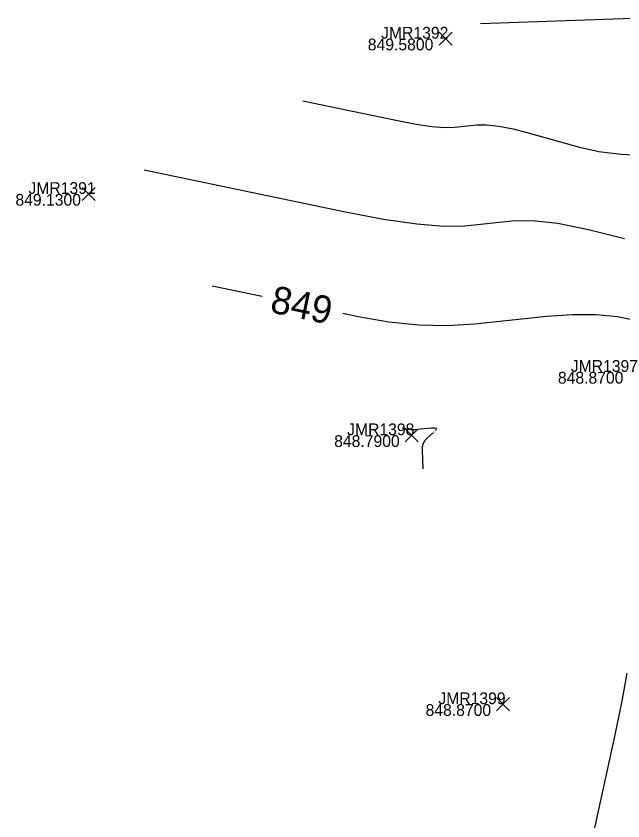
# Model space of a CAD drawing. Extents: x 1654928 to 1810050, y 486881 to 626330.
# Drawn here: x 1801235.5 to 1801297.5, y 489876.6 to 489958.8 of the extents above; entities that cross this region are included whole.
import ezdxf

# ---------------------------------------------------------------- set-up
doc = ezdxf.new("R2010")
doc.units = 0
for name, color, linetype in [('DT_X_Contour_Major', 7, 'Continuous'), ('DT_X_Contour_Minor', 7, 'Continuous'), ('SV_X_Random_Point', 7, 'Continuous'), ('SV_X_Text_Elevation', 7, 'Continuous'), ('SV_X_Text_Name', 7, 'Continuous')]:
    doc.layers.add(name, color=color, linetype=linetype)

msp = doc.modelspace()

# ---------------------------------------------------------------- linework, layer by layer
at = {"layer": 'DT_X_Contour_Major'}
for points in [[(1801260.643, 489930.139), (1801255.532, 489931.208)], [(1801298.897, 489927.653), (1801296.933, 489928.07), (1801294.743, 489928.285), (1801292.327, 489928.298), (1801289.685, 489928.108), (1801282.339, 489927.335), (1801279.529, 489927.164), (1801276.609, 489927.233), (1801273.58, 489927.542), (1801270.44, 489928.09), (1801268.866, 489928.419)], [(1801292.361, 489865.603), (1801296.572, 489884.906), (1801297.355, 489888.668), (1801297.902, 489891.68)]]:
    msp.add_lwpolyline(points, dxfattribs=at)
at = {"layer": 'DT_X_Contour_Minor'}
for points in [[(1801282.925, 489958.029), (1801304.313, 489958.787)], [(1801264.785, 489950.144), (1801274.44, 489948.125), (1801276.357, 489947.758), (1801277.97, 489947.521), (1801279.281, 489947.415), (1801280.287, 489947.44), (1801282.567, 489947.68), (1801283.55, 489947.693), (1801284.787, 489947.553), (1801286.28, 489947.259), (1801288.028, 489946.811), (1801293.028, 489945.412), (1801295.031, 489944.966), (1801297.288, 489944.677), (1801299.798, 489944.544)], [(1801248.586, 489943.096), (1801268.968, 489938.834), (1801273.015, 489938.058), (1801276.422, 489937.559), (1801279.188, 489937.335), (1801281.313, 489937.387), (1801286.126, 489937.894), (1801288.2, 489937.922), (1801290.813, 489937.626), (1801293.964, 489937.005), (1801297.654, 489936.06)], [(1801278.393, 489916.516), (1801278.409, 489916.533), (1801278.42, 489916.66), (1801278.258, 489916.719), (1801277.922, 489916.709), (1801276.798, 489916.59), (1801276.41, 489916.555), (1801276.09, 489916.539), (1801275.837, 489916.543), (1801275.651, 489916.565), (1801274.941, 489916.713)], [(1801277.076, 489912.556), (1801277, 489914.451), (1801277.019, 489914.835), (1801277.11, 489915.176), (1801277.272, 489915.472), (1801277.506, 489915.724), (1801278.092, 489916.223)]]:
    msp.add_lwpolyline(points, dxfattribs=at)
at = {"layer": 'SV_X_Random_Point'}
for p, q in [((1801278.697, 489955.82), (1801280.031, 489957.155)), ((1801278.697, 489957.155), (1801280.031, 489955.82)), ((1801242.25, 489939.962), (1801243.583, 489941.297)), ((1801242.25, 489941.297), (1801243.583, 489939.962)), ((1801275.245, 489915.321), (1801276.578, 489916.656)), ((1801275.245, 489916.656), (1801276.578, 489915.321)), ((1801284.563, 489887.857), (1801285.896, 489889.192)), ((1801284.563, 489889.192), (1801285.896, 489887.857))]:
    msp.add_line(p, q, dxfattribs=at)

# ---------------------------------------------------------------- texts
at = {"layer": 'DT_X_Contour_Major'}
msp.add_text('849', height=2.8, rotation=348.18836, dxfattribs=at).set_placement((1801261.328, 489928.565))
at = {"layer": 'DT_X_Contour_Minor'}
msp.add_text('849', height=0.14, rotation=224.18533, dxfattribs=at).set_placement((1801278.316, 489916.524))
at = {"layer": 'SV_X_Text_Elevation'}
for s, p in [('849.5800', (1801271.418, 489955.287)), ('849.1300', (1801235.424, 489939.429)), ('848.8700', (1801290.835, 489921.258)), ('848.7900', (1801267.984, 489914.789)), ('848.8700', (1801277.321, 489887.325))]:
    msp.add_text(s, height=1.2, dxfattribs=at).set_placement(p)
at = {"layer": 'SV_X_Text_Name'}
for s, p in [('JMR1392', (1801272.779, 489956.487)), ('JMR1391', (1801236.756, 489940.629)), ('JMR1397', (1801292.149, 489922.458)), ('JMR1398', (1801269.308, 489915.989)), ('JMR1399', (1801278.626, 489888.525))]:
    msp.add_text(s, height=1.2, dxfattribs=at).set_placement(p)

doc.saveas('drawing.dxf')
